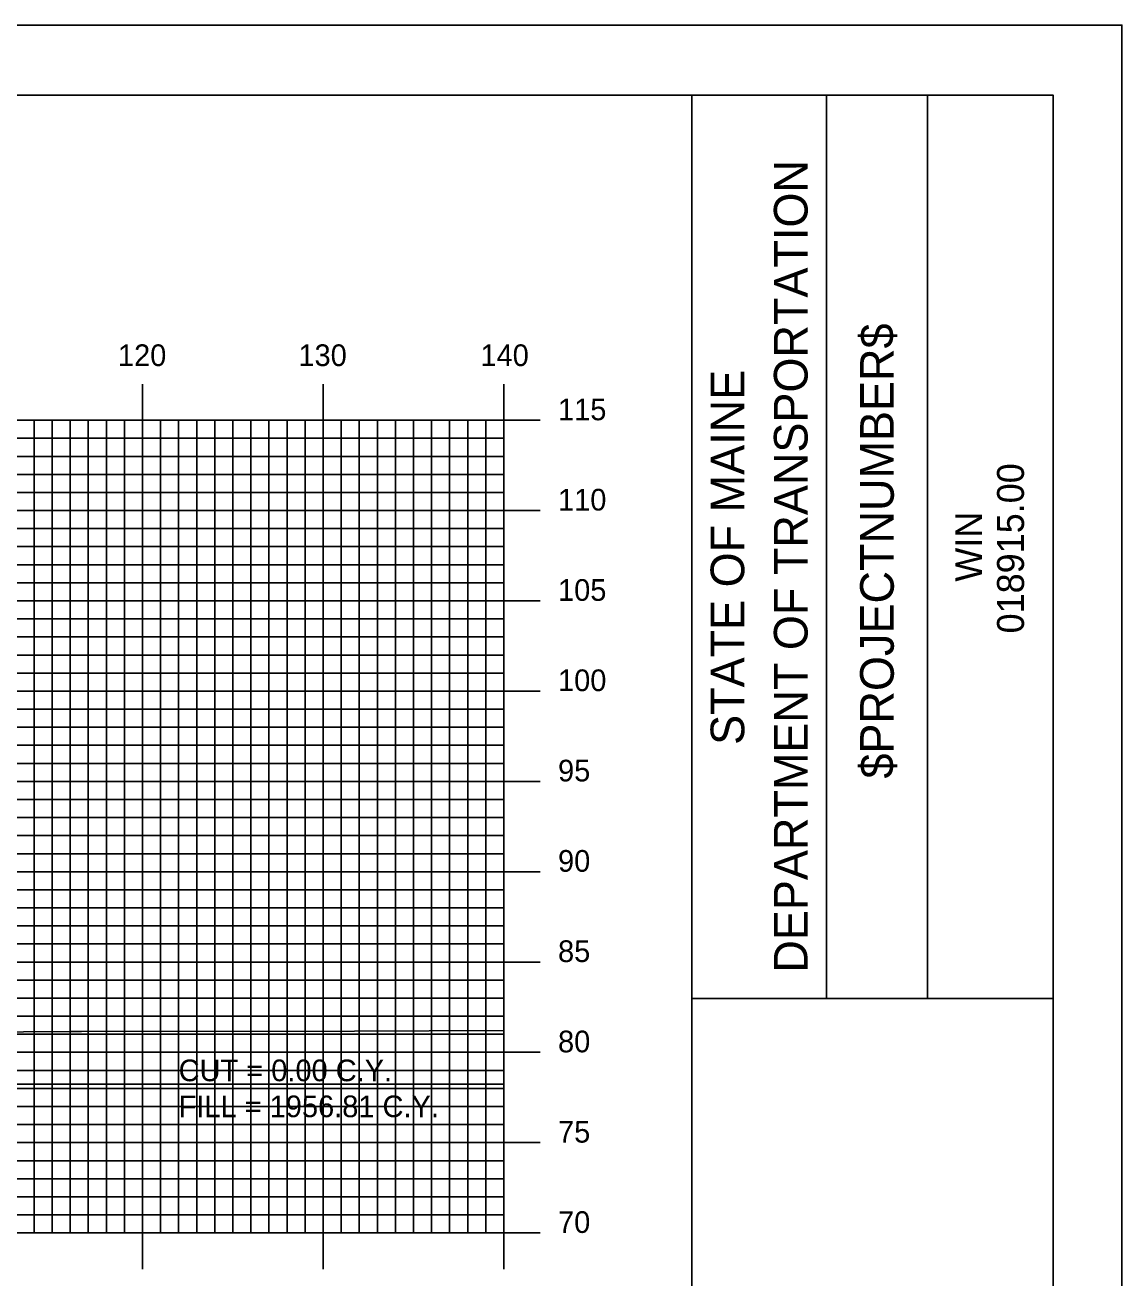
# Model space of a CAD drawing. Extents: x 857504 to 857847, y 364765 to 364985.
# Drawn here: x 857782.8 to 857843.5, y 364915.8 to 364985.2 of the extents above; entities that cross this region are included whole.
import ezdxf

# ---------------------------------------------------------------- set-up
doc = ezdxf.new("R2010")
doc.units = 0
for name, color, linetype in [('BORDER', 7, 'Continuous'), ('D_Roadway_SlopeLines', 7, 'Continuous'), ('D_Text_Standard', 7, 'Continuous'), ('H_V ANNOTATION', 7, 'Continuous'), ('MAJOR', 7, 'Continuous'), ('MINOR', 7, 'Continuous'), ('PLOT BOUNDARY', 7, 'Continuous'), ('S_Roadway_Centerline', 7, 'Continuous')]:
    doc.layers.add(name, color=color, linetype=linetype)

msp = doc.modelspace()

# ---------------------------------------------------------------- linework, layer by layer
at = {"layer": 'BORDER'}
for p, q in [((857819.708, 364771.302), (857819.708, 364981.302)), ((857827.165, 364931.296), (857827.165, 364981.296)), ((857832.755, 364931.296), (857832.755, 364981.296)), ((857819.709, 364931.29), (857839.708, 364931.29))]:
    msp.add_line(p, q, dxfattribs=at)
msp.add_lwpolyline([(857519.708, 364771.302), (857839.708, 364771.302), (857839.708, 364981.302), (857519.708, 364981.302)], close=True, dxfattribs=at)
at = {"layer": 'D_Roadway_SlopeLines'}
msp.add_line((857735.308, 364926.539), (857809.308, 364926.539), dxfattribs=at)
at = {"layer": 'MAJOR'}
for p, q in [((857789.308, 364965.306), (857789.308, 364963.302)), ((857799.308, 364965.306), (857799.308, 364963.302)), ((857809.308, 364965.306), (857809.308, 364963.302)), ((857529.308, 364963.302), (857809.308, 364963.302)), ((857529.308, 364963.302), (857809.308, 364963.302)), ((857789.308, 364918.302), (857789.308, 364963.302)), ((857799.308, 364918.302), (857799.308, 364963.302)), ((857811.312, 364963.302), (857807.304, 364963.302)), ((857809.308, 364918.302), (857809.308, 364963.302)), ((857809.308, 364918.302), (857809.308, 364963.302)), ((857529.308, 364958.302), (857809.308, 364958.302)), ((857811.312, 364958.302), (857807.304, 364958.302)), ((857529.308, 364953.302), (857809.308, 364953.302)), ((857811.312, 364953.302), (857807.304, 364953.302)), ((857529.308, 364948.302), (857809.308, 364948.302)), ((857811.312, 364948.302), (857807.304, 364948.302)), ((857529.308, 364943.302), (857809.308, 364943.302)), ((857811.312, 364943.302), (857807.304, 364943.302)), ((857529.308, 364938.302), (857809.308, 364938.302)), ((857811.312, 364938.302), (857807.304, 364938.302)), ((857529.308, 364933.302), (857809.308, 364933.302)), ((857811.312, 364933.302), (857807.304, 364933.302)), ((857529.308, 364928.302), (857809.308, 364928.302)), ((857811.312, 364928.302), (857807.304, 364928.302)), ((857529.308, 364923.302), (857809.308, 364923.302)), ((857811.312, 364923.302), (857807.304, 364923.302)), ((857529.308, 364918.302), (857809.308, 364918.302)), ((857529.308, 364918.302), (857809.308, 364918.302)), ((857789.308, 364916.298), (857789.308, 364918.302)), ((857799.308, 364916.298), (857799.308, 364918.302)), ((857811.312, 364918.302), (857807.304, 364918.302)), ((857809.308, 364916.298), (857809.308, 364918.302))]:
    msp.add_line(p, q, dxfattribs=at)
at = {"layer": 'MINOR'}
for p, q in [((857783.308, 364918.302), (857783.308, 364963.302)), ((857784.308, 364918.302), (857784.308, 364963.302)), ((857785.308, 364918.302), (857785.308, 364963.302)), ((857786.308, 364918.302), (857786.308, 364963.302)), ((857787.308, 364918.302), (857787.308, 364963.302)), ((857788.308, 364918.302), (857788.308, 364963.302)), ((857790.308, 364918.302), (857790.308, 364963.302)), ((857791.308, 364918.302), (857791.308, 364963.302)), ((857792.308, 364918.302), (857792.308, 364963.302)), ((857793.308, 364918.302), (857793.308, 364963.302)), ((857794.308, 364918.302), (857794.308, 364963.302)), ((857795.308, 364918.302), (857795.308, 364963.302)), ((857796.308, 364918.302), (857796.308, 364963.302)), ((857797.308, 364918.302), (857797.308, 364963.302)), ((857798.308, 364918.302), (857798.308, 364963.302)), ((857800.308, 364918.302), (857800.308, 364963.302)), ((857801.308, 364918.302), (857801.308, 364963.302)), ((857802.308, 364918.302), (857802.308, 364963.302)), ((857803.308, 364918.302), (857803.308, 364963.302)), ((857804.308, 364918.302), (857804.308, 364963.302)), ((857805.308, 364918.302), (857805.308, 364963.302)), ((857806.308, 364918.302), (857806.308, 364963.302)), ((857807.308, 364918.302), (857807.308, 364963.302)), ((857808.308, 364918.302), (857808.308, 364963.302)), ((857529.308, 364962.302), (857809.308, 364962.302)), ((857809.308, 364962.302), (857807.304, 364962.302)), ((857529.308, 364961.302), (857809.308, 364961.302)), ((857809.308, 364961.302), (857807.304, 364961.302)), ((857529.308, 364960.302), (857809.308, 364960.302)), ((857809.308, 364960.302), (857807.304, 364960.302)), ((857529.308, 364959.302), (857809.308, 364959.302)), ((857809.308, 364959.302), (857807.304, 364959.302)), ((857529.308, 364957.302), (857809.308, 364957.302)), ((857809.308, 364957.302), (857807.304, 364957.302)), ((857529.308, 364956.302), (857809.308, 364956.302)), ((857809.308, 364956.302), (857807.304, 364956.302)), ((857529.308, 364955.302), (857809.308, 364955.302)), ((857809.308, 364955.302), (857807.304, 364955.302)), ((857529.308, 364954.302), (857809.308, 364954.302)), ((857809.308, 364954.302), (857807.304, 364954.302)), ((857529.308, 364952.302), (857809.308, 364952.302)), ((857809.308, 364952.302), (857807.304, 364952.302)), ((857529.308, 364951.302), (857809.308, 364951.302)), ((857809.308, 364951.302), (857807.304, 364951.302)), ((857529.308, 364950.302), (857809.308, 364950.302)), ((857809.308, 364950.302), (857807.304, 364950.302)), ((857529.308, 364949.302), (857809.308, 364949.302)), ((857809.308, 364949.302), (857807.304, 364949.302)), ((857529.308, 364947.302), (857809.308, 364947.302)), ((857809.308, 364947.302), (857807.304, 364947.302)), ((857529.308, 364946.302), (857809.308, 364946.302)), ((857809.308, 364946.302), (857807.304, 364946.302)), ((857529.308, 364945.302), (857809.308, 364945.302)), ((857809.308, 364945.302), (857807.304, 364945.302)), ((857529.308, 364944.302), (857809.308, 364944.302)), ((857809.308, 364944.302), (857807.304, 364944.302)), ((857529.308, 364942.302), (857809.308, 364942.302)), ((857809.308, 364942.302), (857807.304, 364942.302)), ((857529.308, 364941.302), (857809.308, 364941.302)), ((857809.308, 364941.302), (857807.304, 364941.302)), ((857529.308, 364940.302), (857809.308, 364940.302)), ((857809.308, 364940.302), (857807.304, 364940.302)), ((857529.308, 364939.302), (857809.308, 364939.302)), ((857809.308, 364939.302), (857807.304, 364939.302)), ((857529.308, 364937.302), (857809.308, 364937.302)), ((857809.308, 364937.302), (857807.304, 364937.302)), ((857529.308, 364936.302), (857809.308, 364936.302)), ((857809.308, 364936.302), (857807.304, 364936.302)), ((857529.308, 364935.302), (857809.308, 364935.302)), ((857809.308, 364935.302), (857807.304, 364935.302)), ((857529.308, 364934.302), (857809.308, 364934.302)), ((857809.308, 364934.302), (857807.304, 364934.302)), ((857529.308, 364932.302), (857809.308, 364932.302)), ((857809.308, 364932.302), (857807.304, 364932.302)), ((857529.308, 364931.302), (857809.308, 364931.302)), ((857809.308, 364931.302), (857807.304, 364931.302)), ((857529.308, 364930.302), (857809.308, 364930.302)), ((857809.308, 364930.302), (857807.304, 364930.302)), ((857529.308, 364929.302), (857809.308, 364929.302)), ((857809.308, 364929.302), (857807.304, 364929.302)), ((857529.308, 364927.302), (857809.308, 364927.302)), ((857809.308, 364927.302), (857807.304, 364927.302)), ((857529.308, 364926.302), (857809.308, 364926.302)), ((857809.308, 364926.302), (857807.304, 364926.302)), ((857529.308, 364925.302), (857809.308, 364925.302)), ((857809.308, 364925.302), (857807.304, 364925.302)), ((857529.308, 364924.302), (857809.308, 364924.302)), ((857809.308, 364924.302), (857807.304, 364924.302)), ((857529.308, 364922.302), (857809.308, 364922.302)), ((857809.308, 364922.302), (857807.304, 364922.302)), ((857529.308, 364921.302), (857809.308, 364921.302)), ((857809.308, 364921.302), (857807.304, 364921.302)), ((857529.308, 364920.302), (857809.308, 364920.302)), ((857809.308, 364920.302), (857807.304, 364920.302)), ((857529.308, 364919.302), (857809.308, 364919.302)), ((857809.308, 364919.302), (857807.304, 364919.302))]:
    msp.add_line(p, q, dxfattribs=at)
at = {"layer": 'PLOT BOUNDARY'}
msp.add_lwpolyline([(857503.521, 364765.184), (857843.521, 364765.184), (857843.521, 364985.184), (857503.521, 364985.184)], close=True, dxfattribs=at)
at = {"layer": 'S_Roadway_Centerline'}
msp.add_lwpolyline([(857714.491, 364924.707), (857723.7, 364923.452), (857723.875, 364923.476), (857724.627, 364923.626), (857729.419, 364924.342), (857730.665, 364924.767), (857732.057, 364925.31), (857732.425, 364925.446), (857732.667, 364925.491), (857732.758, 364925.539), (857735.045, 364926.522), (857737.697, 364927.904), (857750.562, 364928.741), (857755.69, 364929.224), (857762.41, 364929.29), (857785.258, 364929.461), (857785.627, 364929.463), (857785.734, 364929.462), (857785.931, 364929.461), (857801.042, 364929.474), (857809.308, 364929.511)], dxfattribs=at)

# ---------------------------------------------------------------- texts
at = {"layer": 'BORDER'}
for s, height, p in [('DEPARTMENT OF TRANSPORTATION', 1.86351, (857826.121, 364932.714)), ('$PROJECTNUMBER$', 1.86351, (857830.892, 364943.46)), ('STATE OF MAINE', 1.86351, (857822.618, 364945.326)), ('018915.00', 1.4905, (857838.099, 364951.498)), ('WIN', 1.4905, (857835.781, 364954.362))]:
    msp.add_text(s, height=height, rotation=90, dxfattribs=at).set_placement(p)
at = {"layer": 'D_Text_Standard'}
for s, p in [('CUT = 0.00 C.Y.', (857791.308, 364926.702)), ('FILL = 1956.81 C.Y.', (857791.308, 364924.71))]:
    msp.add_text(s, height=1.2, dxfattribs=at).set_placement(p)
at = {"layer": 'H_V ANNOTATION'}
for s, p in [('120', (857787.948, 364966.302)), ('130', (857797.938, 364966.302)), ('140', (857808.013, 364966.302)), ('115', (857812.308, 364963.302)), ('110', (857812.308, 364958.302)), ('105', (857812.308, 364953.302)), ('100', (857812.308, 364948.302)), ('95', (857812.308, 364943.302)), ('90', (857812.308, 364938.302)), ('85', (857812.308, 364933.302)), ('80', (857812.308, 364928.302)), ('75', (857812.308, 364923.302)), ('70', (857812.308, 364918.302))]:
    msp.add_text(s, height=1.2, dxfattribs=at).set_placement(p)

doc.saveas('drawing.dxf')
